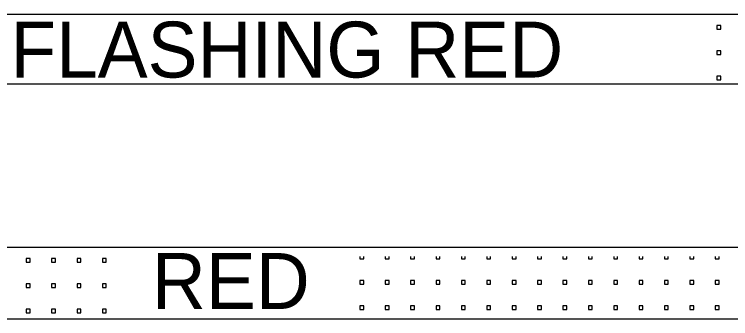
# Model space of a CAD drawing. Extents: x 10000 to 10825, y 10000 to 10530.
# Drawn here: x 10652.19 to 10697.01, y 10135.91 to 10154.98 of the extents above; entities that cross this region are included whole.
import ezdxf

# ---------------------------------------------------------------- set-up
doc = ezdxf.new("R2010")
doc.units = 0
doc.layers.add('Default', color=7, linetype='Continuous')
doc.layers.add('TextStructures', color=7, linetype='Continuous')

msp = doc.modelspace()

# ---------------------------------------------------------------- linework, layer by layer
at = {"layer": 'Default'}
for p, q in [((10490.187, 10154.98), (10784.11, 10154.98)), ((10490.187, 10150.62), (10784.11, 10150.62)), ((10490.187, 10140.399), (10784.11, 10140.399)), ((10490.187, 10135.911), (10784.11, 10135.911))]:
    msp.add_line(p, q, dxfattribs=at)
for points in [[(10696.389, 10154.045), (10696.389, 10154.285), (10696.153, 10154.283), (10696.153, 10154.045), (10696.389, 10154.045)], [(10696.389, 10154.045), (10696.389, 10154.285), (10696.153, 10154.283), (10696.153, 10154.045), (10696.389, 10154.045)], [(10696.389, 10152.458), (10696.389, 10152.696), (10696.153, 10152.695), (10696.153, 10152.458), (10696.389, 10152.458)], [(10696.389, 10152.458), (10696.389, 10152.696), (10696.153, 10152.695), (10696.153, 10152.458), (10696.389, 10152.458)], [(10696.389, 10150.869), (10696.389, 10151.109), (10696.153, 10151.107), (10696.153, 10150.869), (10696.389, 10150.869)], [(10696.389, 10150.869), (10696.389, 10151.109), (10696.153, 10151.107), (10696.153, 10150.869), (10696.389, 10150.869)], [(10653.179, 10139.448), (10653.179, 10139.688), (10652.942, 10139.687), (10652.942, 10139.448), (10653.179, 10139.448)], [(10653.179, 10139.448), (10653.179, 10139.688), (10652.942, 10139.687), (10652.942, 10139.448), (10653.179, 10139.448)], [(10654.765, 10139.448), (10654.765, 10139.688), (10654.529, 10139.687), (10654.529, 10139.448), (10654.765, 10139.448)], [(10654.765, 10139.448), (10654.765, 10139.688), (10654.529, 10139.687), (10654.529, 10139.448), (10654.765, 10139.448)], [(10656.355, 10139.448), (10656.355, 10139.688), (10656.119, 10139.687), (10656.119, 10139.448), (10656.355, 10139.448)], [(10656.355, 10139.448), (10656.355, 10139.688), (10656.119, 10139.687), (10656.119, 10139.448), (10656.355, 10139.448)], [(10657.942, 10139.448), (10657.942, 10139.688), (10657.705, 10139.687), (10657.705, 10139.448), (10657.942, 10139.448)], [(10657.942, 10139.448), (10657.942, 10139.688), (10657.705, 10139.687), (10657.705, 10139.448), (10657.942, 10139.448)], [(10673.814, 10139.805), (10673.814, 10139.662)], [(10673.814, 10139.805), (10673.814, 10139.662)], [(10673.814, 10139.662), (10674.053, 10139.662)], [(10673.814, 10139.662), (10674.053, 10139.662)], [(10674.053, 10139.662), (10674.053, 10139.805)], [(10674.053, 10139.662), (10674.053, 10139.805)], [(10675.404, 10139.805), (10675.404, 10139.662)], [(10675.404, 10139.805), (10675.404, 10139.662)], [(10675.404, 10139.662), (10675.641, 10139.662)], [(10675.404, 10139.662), (10675.641, 10139.662)], [(10675.641, 10139.662), (10675.641, 10139.805)], [(10675.641, 10139.662), (10675.641, 10139.805)], [(10676.991, 10139.805), (10676.991, 10139.662)], [(10676.991, 10139.805), (10676.991, 10139.662)], [(10676.991, 10139.662), (10677.229, 10139.662)], [(10676.991, 10139.662), (10677.229, 10139.662)], [(10677.229, 10139.662), (10677.229, 10139.805)], [(10677.229, 10139.662), (10677.229, 10139.805)], [(10678.58, 10139.805), (10678.58, 10139.662)], [(10678.58, 10139.805), (10678.58, 10139.662)], [(10678.58, 10139.662), (10678.817, 10139.662)], [(10678.58, 10139.662), (10678.817, 10139.662)], [(10678.817, 10139.662), (10678.817, 10139.805)], [(10678.817, 10139.662), (10678.817, 10139.805)], [(10680.167, 10139.805), (10680.167, 10139.662)], [(10680.167, 10139.805), (10680.167, 10139.662)], [(10680.167, 10139.662), (10680.406, 10139.662)], [(10680.167, 10139.662), (10680.406, 10139.662)], [(10680.406, 10139.662), (10680.406, 10139.805)], [(10680.406, 10139.662), (10680.406, 10139.805)], [(10681.756, 10139.805), (10681.756, 10139.662)], [(10681.756, 10139.805), (10681.756, 10139.662)], [(10681.756, 10139.662), (10681.993, 10139.662)], [(10681.756, 10139.662), (10681.993, 10139.662)], [(10681.993, 10139.662), (10681.993, 10139.805)], [(10681.993, 10139.662), (10681.993, 10139.805)], [(10683.343, 10139.805), (10683.343, 10139.662)], [(10683.343, 10139.805), (10683.343, 10139.662)], [(10683.343, 10139.662), (10683.582, 10139.662)], [(10683.343, 10139.662), (10683.582, 10139.662)], [(10683.582, 10139.662), (10683.582, 10139.805)], [(10683.582, 10139.662), (10683.582, 10139.805)], [(10684.933, 10139.805), (10684.933, 10139.662)], [(10684.933, 10139.805), (10684.933, 10139.662)], [(10684.933, 10139.662), (10685.169, 10139.662)], [(10684.933, 10139.662), (10685.169, 10139.662)], [(10685.169, 10139.662), (10685.169, 10139.805)], [(10685.169, 10139.662), (10685.169, 10139.805)], [(10686.519, 10139.805), (10686.519, 10139.662)], [(10686.519, 10139.805), (10686.519, 10139.662)], [(10686.519, 10139.662), (10686.758, 10139.662)], [(10686.519, 10139.662), (10686.758, 10139.662)], [(10686.758, 10139.662), (10686.758, 10139.805)], [(10686.758, 10139.662), (10686.758, 10139.805)], [(10688.109, 10139.805), (10688.109, 10139.662)], [(10688.109, 10139.805), (10688.109, 10139.662)], [(10688.109, 10139.662), (10688.345, 10139.662)], [(10688.109, 10139.662), (10688.345, 10139.662)], [(10688.345, 10139.662), (10688.345, 10139.805)], [(10688.345, 10139.662), (10688.345, 10139.805)], [(10689.695, 10139.805), (10689.695, 10139.662)], [(10689.695, 10139.805), (10689.695, 10139.662)], [(10689.695, 10139.662), (10689.934, 10139.662)], [(10689.695, 10139.662), (10689.934, 10139.662)], [(10689.934, 10139.662), (10689.934, 10139.805)], [(10689.934, 10139.662), (10689.934, 10139.805)], [(10691.285, 10139.805), (10691.285, 10139.662)], [(10691.285, 10139.805), (10691.285, 10139.662)], [(10691.285, 10139.662), (10691.522, 10139.662)], [(10691.285, 10139.662), (10691.522, 10139.662)], [(10691.522, 10139.662), (10691.522, 10139.805)], [(10691.522, 10139.662), (10691.522, 10139.805)], [(10692.871, 10139.805), (10692.871, 10139.662)], [(10692.871, 10139.805), (10692.871, 10139.662)], [(10692.871, 10139.662), (10693.11, 10139.662)], [(10692.871, 10139.662), (10693.11, 10139.662)], [(10693.11, 10139.662), (10693.11, 10139.805)], [(10693.11, 10139.662), (10693.11, 10139.805)], [(10694.461, 10139.805), (10694.461, 10139.662)], [(10694.461, 10139.805), (10694.461, 10139.662)], [(10694.461, 10139.662), (10694.698, 10139.662)], [(10694.461, 10139.662), (10694.698, 10139.662)], [(10694.698, 10139.662), (10694.698, 10139.805)], [(10694.698, 10139.662), (10694.698, 10139.805)], [(10696.048, 10139.805), (10696.048, 10139.662)], [(10696.048, 10139.805), (10696.048, 10139.662)], [(10696.048, 10139.662), (10696.286, 10139.662)], [(10696.048, 10139.662), (10696.286, 10139.662)], [(10696.286, 10139.662), (10696.286, 10139.805)], [(10696.286, 10139.662), (10696.286, 10139.805)], [(10674.053, 10138.075), (10674.053, 10138.314), (10673.814, 10138.313), (10673.814, 10138.075), (10674.053, 10138.075)], [(10674.053, 10138.075), (10674.053, 10138.314), (10673.814, 10138.313), (10673.814, 10138.075), (10674.053, 10138.075)], [(10675.641, 10138.075), (10675.641, 10138.314), (10675.404, 10138.313), (10675.404, 10138.075), (10675.641, 10138.075)], [(10675.641, 10138.075), (10675.641, 10138.314), (10675.404, 10138.313), (10675.404, 10138.075), (10675.641, 10138.075)], [(10677.229, 10138.075), (10677.229, 10138.314), (10676.991, 10138.313), (10676.991, 10138.075), (10677.229, 10138.075)], [(10677.229, 10138.075), (10677.229, 10138.314), (10676.991, 10138.313), (10676.991, 10138.075), (10677.229, 10138.075)], [(10678.817, 10138.075), (10678.817, 10138.314), (10678.58, 10138.313), (10678.58, 10138.075), (10678.817, 10138.075)], [(10678.817, 10138.075), (10678.817, 10138.314), (10678.58, 10138.313), (10678.58, 10138.075), (10678.817, 10138.075)], [(10680.406, 10138.075), (10680.406, 10138.314), (10680.167, 10138.313), (10680.167, 10138.075), (10680.406, 10138.075)], [(10680.406, 10138.075), (10680.406, 10138.314), (10680.167, 10138.313), (10680.167, 10138.075), (10680.406, 10138.075)], [(10681.993, 10138.075), (10681.993, 10138.314), (10681.756, 10138.313), (10681.756, 10138.075), (10681.993, 10138.075)], [(10681.993, 10138.075), (10681.993, 10138.314), (10681.756, 10138.313), (10681.756, 10138.075), (10681.993, 10138.075)], [(10683.582, 10138.075), (10683.582, 10138.314), (10683.343, 10138.313), (10683.343, 10138.075), (10683.582, 10138.075)], [(10683.582, 10138.075), (10683.582, 10138.314), (10683.343, 10138.313), (10683.343, 10138.075), (10683.582, 10138.075)], [(10685.169, 10138.075), (10685.169, 10138.314), (10684.933, 10138.313), (10684.933, 10138.075), (10685.169, 10138.075)], [(10685.169, 10138.075), (10685.169, 10138.314), (10684.933, 10138.313), (10684.933, 10138.075), (10685.169, 10138.075)], [(10686.758, 10138.075), (10686.758, 10138.314), (10686.519, 10138.313), (10686.519, 10138.075), (10686.758, 10138.075)], [(10686.758, 10138.075), (10686.758, 10138.314), (10686.519, 10138.313), (10686.519, 10138.075), (10686.758, 10138.075)], [(10688.345, 10138.075), (10688.345, 10138.314), (10688.109, 10138.313), (10688.109, 10138.075), (10688.345, 10138.075)], [(10688.345, 10138.075), (10688.345, 10138.314), (10688.109, 10138.313), (10688.109, 10138.075), (10688.345, 10138.075)], [(10689.934, 10138.075), (10689.934, 10138.314), (10689.695, 10138.313), (10689.695, 10138.075), (10689.934, 10138.075)], [(10689.934, 10138.075), (10689.934, 10138.314), (10689.695, 10138.313), (10689.695, 10138.075), (10689.934, 10138.075)], [(10691.522, 10138.075), (10691.522, 10138.314), (10691.285, 10138.313), (10691.285, 10138.075), (10691.522, 10138.075)], [(10691.522, 10138.075), (10691.522, 10138.314), (10691.285, 10138.313), (10691.285, 10138.075), (10691.522, 10138.075)], [(10693.11, 10138.075), (10693.11, 10138.314), (10692.871, 10138.313), (10692.871, 10138.075), (10693.11, 10138.075)], [(10693.11, 10138.075), (10693.11, 10138.314), (10692.871, 10138.313), (10692.871, 10138.075), (10693.11, 10138.075)], [(10694.698, 10138.075), (10694.698, 10138.314), (10694.461, 10138.313), (10694.461, 10138.075), (10694.698, 10138.075)], [(10694.698, 10138.075), (10694.698, 10138.314), (10694.461, 10138.313), (10694.461, 10138.075), (10694.698, 10138.075)], [(10696.286, 10138.075), (10696.286, 10138.314), (10696.048, 10138.313), (10696.048, 10138.075), (10696.286, 10138.075)], [(10696.286, 10138.075), (10696.286, 10138.314), (10696.048, 10138.313), (10696.048, 10138.075), (10696.286, 10138.075)], [(10653.179, 10137.861), (10653.179, 10138.1), (10652.942, 10138.099), (10652.942, 10137.861), (10653.179, 10137.861)], [(10653.179, 10137.861), (10653.179, 10138.1), (10652.942, 10138.099), (10652.942, 10137.861), (10653.179, 10137.861)], [(10654.765, 10137.861), (10654.765, 10138.1), (10654.529, 10138.099), (10654.529, 10137.861), (10654.765, 10137.861)], [(10654.765, 10137.861), (10654.765, 10138.1), (10654.529, 10138.099), (10654.529, 10137.861), (10654.765, 10137.861)], [(10656.355, 10137.861), (10656.355, 10138.1), (10656.119, 10138.099), (10656.119, 10137.861), (10656.355, 10137.861)], [(10656.355, 10137.861), (10656.355, 10138.1), (10656.119, 10138.099), (10656.119, 10137.861), (10656.355, 10137.861)], [(10657.942, 10137.861), (10657.942, 10138.1), (10657.705, 10138.099), (10657.705, 10137.861), (10657.942, 10137.861)], [(10657.942, 10137.861), (10657.942, 10138.1), (10657.705, 10138.099), (10657.705, 10137.861), (10657.942, 10137.861)], [(10653.179, 10136.272), (10653.179, 10136.512), (10652.942, 10136.511), (10652.942, 10136.272), (10653.179, 10136.272)], [(10653.179, 10136.272), (10653.179, 10136.512), (10652.942, 10136.511), (10652.942, 10136.272), (10653.179, 10136.272)], [(10654.765, 10136.272), (10654.765, 10136.512), (10654.529, 10136.511), (10654.529, 10136.272), (10654.765, 10136.272)], [(10654.765, 10136.272), (10654.765, 10136.512), (10654.529, 10136.511), (10654.529, 10136.272), (10654.765, 10136.272)], [(10656.355, 10136.272), (10656.355, 10136.512), (10656.119, 10136.511), (10656.119, 10136.272), (10656.355, 10136.272)], [(10656.355, 10136.272), (10656.355, 10136.512), (10656.119, 10136.511), (10656.119, 10136.272), (10656.355, 10136.272)], [(10657.942, 10136.272), (10657.942, 10136.512), (10657.705, 10136.511), (10657.705, 10136.272), (10657.942, 10136.272)], [(10657.942, 10136.272), (10657.942, 10136.512), (10657.705, 10136.511), (10657.705, 10136.272), (10657.942, 10136.272)], [(10674.053, 10136.486), (10674.053, 10136.726), (10673.814, 10136.724), (10673.814, 10136.486), (10674.053, 10136.486)], [(10674.053, 10136.486), (10674.053, 10136.726), (10673.814, 10136.724), (10673.814, 10136.486), (10674.053, 10136.486)], [(10675.641, 10136.486), (10675.641, 10136.726), (10675.404, 10136.724), (10675.404, 10136.486), (10675.641, 10136.486)], [(10675.641, 10136.486), (10675.641, 10136.726), (10675.404, 10136.724), (10675.404, 10136.486), (10675.641, 10136.486)], [(10677.229, 10136.486), (10677.229, 10136.726), (10676.991, 10136.724), (10676.991, 10136.486), (10677.229, 10136.486)], [(10677.229, 10136.486), (10677.229, 10136.726), (10676.991, 10136.724), (10676.991, 10136.486), (10677.229, 10136.486)], [(10678.817, 10136.486), (10678.817, 10136.726), (10678.58, 10136.724), (10678.58, 10136.486), (10678.817, 10136.486)], [(10678.817, 10136.486), (10678.817, 10136.726), (10678.58, 10136.724), (10678.58, 10136.486), (10678.817, 10136.486)], [(10680.406, 10136.486), (10680.406, 10136.726), (10680.167, 10136.724), (10680.167, 10136.486), (10680.406, 10136.486)], [(10680.406, 10136.486), (10680.406, 10136.726), (10680.167, 10136.724), (10680.167, 10136.486), (10680.406, 10136.486)], [(10681.993, 10136.486), (10681.993, 10136.726), (10681.756, 10136.724), (10681.756, 10136.486), (10681.993, 10136.486)], [(10681.993, 10136.486), (10681.993, 10136.726), (10681.756, 10136.724), (10681.756, 10136.486), (10681.993, 10136.486)], [(10683.582, 10136.486), (10683.582, 10136.726), (10683.343, 10136.724), (10683.343, 10136.486), (10683.582, 10136.486)], [(10683.582, 10136.486), (10683.582, 10136.726), (10683.343, 10136.724), (10683.343, 10136.486), (10683.582, 10136.486)], [(10685.169, 10136.486), (10685.169, 10136.726), (10684.933, 10136.724), (10684.933, 10136.486), (10685.169, 10136.486)], [(10685.169, 10136.486), (10685.169, 10136.726), (10684.933, 10136.724), (10684.933, 10136.486), (10685.169, 10136.486)], [(10686.758, 10136.486), (10686.758, 10136.726), (10686.519, 10136.724), (10686.519, 10136.486), (10686.758, 10136.486)], [(10686.758, 10136.486), (10686.758, 10136.726), (10686.519, 10136.724), (10686.519, 10136.486), (10686.758, 10136.486)], [(10688.345, 10136.486), (10688.345, 10136.726), (10688.109, 10136.724), (10688.109, 10136.486), (10688.345, 10136.486)], [(10688.345, 10136.486), (10688.345, 10136.726), (10688.109, 10136.724), (10688.109, 10136.486), (10688.345, 10136.486)], [(10689.934, 10136.486), (10689.934, 10136.726), (10689.695, 10136.724), (10689.695, 10136.486), (10689.934, 10136.486)], [(10689.934, 10136.486), (10689.934, 10136.726), (10689.695, 10136.724), (10689.695, 10136.486), (10689.934, 10136.486)], [(10691.522, 10136.486), (10691.522, 10136.726), (10691.285, 10136.724), (10691.285, 10136.486), (10691.522, 10136.486)], [(10691.522, 10136.486), (10691.522, 10136.726), (10691.285, 10136.724), (10691.285, 10136.486), (10691.522, 10136.486)], [(10693.11, 10136.486), (10693.11, 10136.726), (10692.871, 10136.724), (10692.871, 10136.486), (10693.11, 10136.486)], [(10693.11, 10136.486), (10693.11, 10136.726), (10692.871, 10136.724), (10692.871, 10136.486), (10693.11, 10136.486)], [(10694.698, 10136.486), (10694.698, 10136.726), (10694.461, 10136.724), (10694.461, 10136.486), (10694.698, 10136.486)], [(10694.698, 10136.486), (10694.698, 10136.726), (10694.461, 10136.724), (10694.461, 10136.486), (10694.698, 10136.486)], [(10696.286, 10136.486), (10696.286, 10136.726), (10696.048, 10136.724), (10696.048, 10136.486), (10696.286, 10136.486)], [(10696.286, 10136.486), (10696.286, 10136.726), (10696.048, 10136.724), (10696.048, 10136.486), (10696.286, 10136.486)]]:
    msp.add_lwpolyline(points, dxfattribs=at)

# ---------------------------------------------------------------- texts
at = {"layer": 'TextStructures'}
for s, p in [('FLASHING RED', (10651.948, 10151.02)), ('RED', (10660.796, 10136.521))]:
    msp.add_text(s, height=3.5, rotation=0.0007, dxfattribs=at).set_placement(p)

doc.saveas('drawing.dxf')
